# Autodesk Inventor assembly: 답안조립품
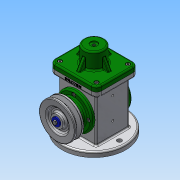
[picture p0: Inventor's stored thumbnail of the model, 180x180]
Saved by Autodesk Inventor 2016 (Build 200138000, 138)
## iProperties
Created: 2018-10
Part Number: 답안조립품
Material: 일반
Document SubType Name: Assembly
Designer: Administrator
Author: Administrator
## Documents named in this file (18)
- C:\Users\Administrator\Desktop\481007V1046\답안조립품.iam
- C:\Users\Administrator\Desktop\481007V1046\본체.ipt
- C:\Users\Administrator\Desktop\481007V1046\앞커버.ipt
- C:\Users\Administrator\Desktop\481007V1046\뒤커버.ipt
- C:\Users\Administrator\Desktop\481007V1046\베어링 17 x 40 x 12.ipt
- C:\Users\Administrator\Desktop\481007V1046\편심축.ipt
- C:\Users\Administrator\Desktop\481007V1046\오일 실 17 30 8.ipt
- C:\Users\Administrator\Desktop\481007V1046\링크.ipt
- C:\Users\Administrator\Desktop\481007V1046\슬라이더.ipt
- C:\Users\Administrator\Desktop\481007V1046\클레비스 핀 6 x 22.ipt
- 클레비스 핀 6 x 22.ipt
- C:\Users\Administrator\Desktop\481007V1046\E-링.ipt
- C:\Users\Administrator\Desktop\481007V1046\키 4 x 4 x 12.ipt
- C:\Users\Administrator\Desktop\481007V1046\V-벨트풀리.ipt
- C:\Users\Administrator\Desktop\481007V1046\덮개.ipt
- C:\Users\Administrator\Desktop\481007V1046\와셔 4x16.ipt
- C:\Users\Administrator\Desktop\481007V1046\볼트 M4 x 10.ipt
- C:\Users\Administrator\Desktop\481007V1046\볼트 M4 x 8.ipt
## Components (2 placed, 2 different names)
1. E-링:1
2. V-벨트풀리:2
